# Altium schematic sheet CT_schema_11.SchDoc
size 742 x 377 mm
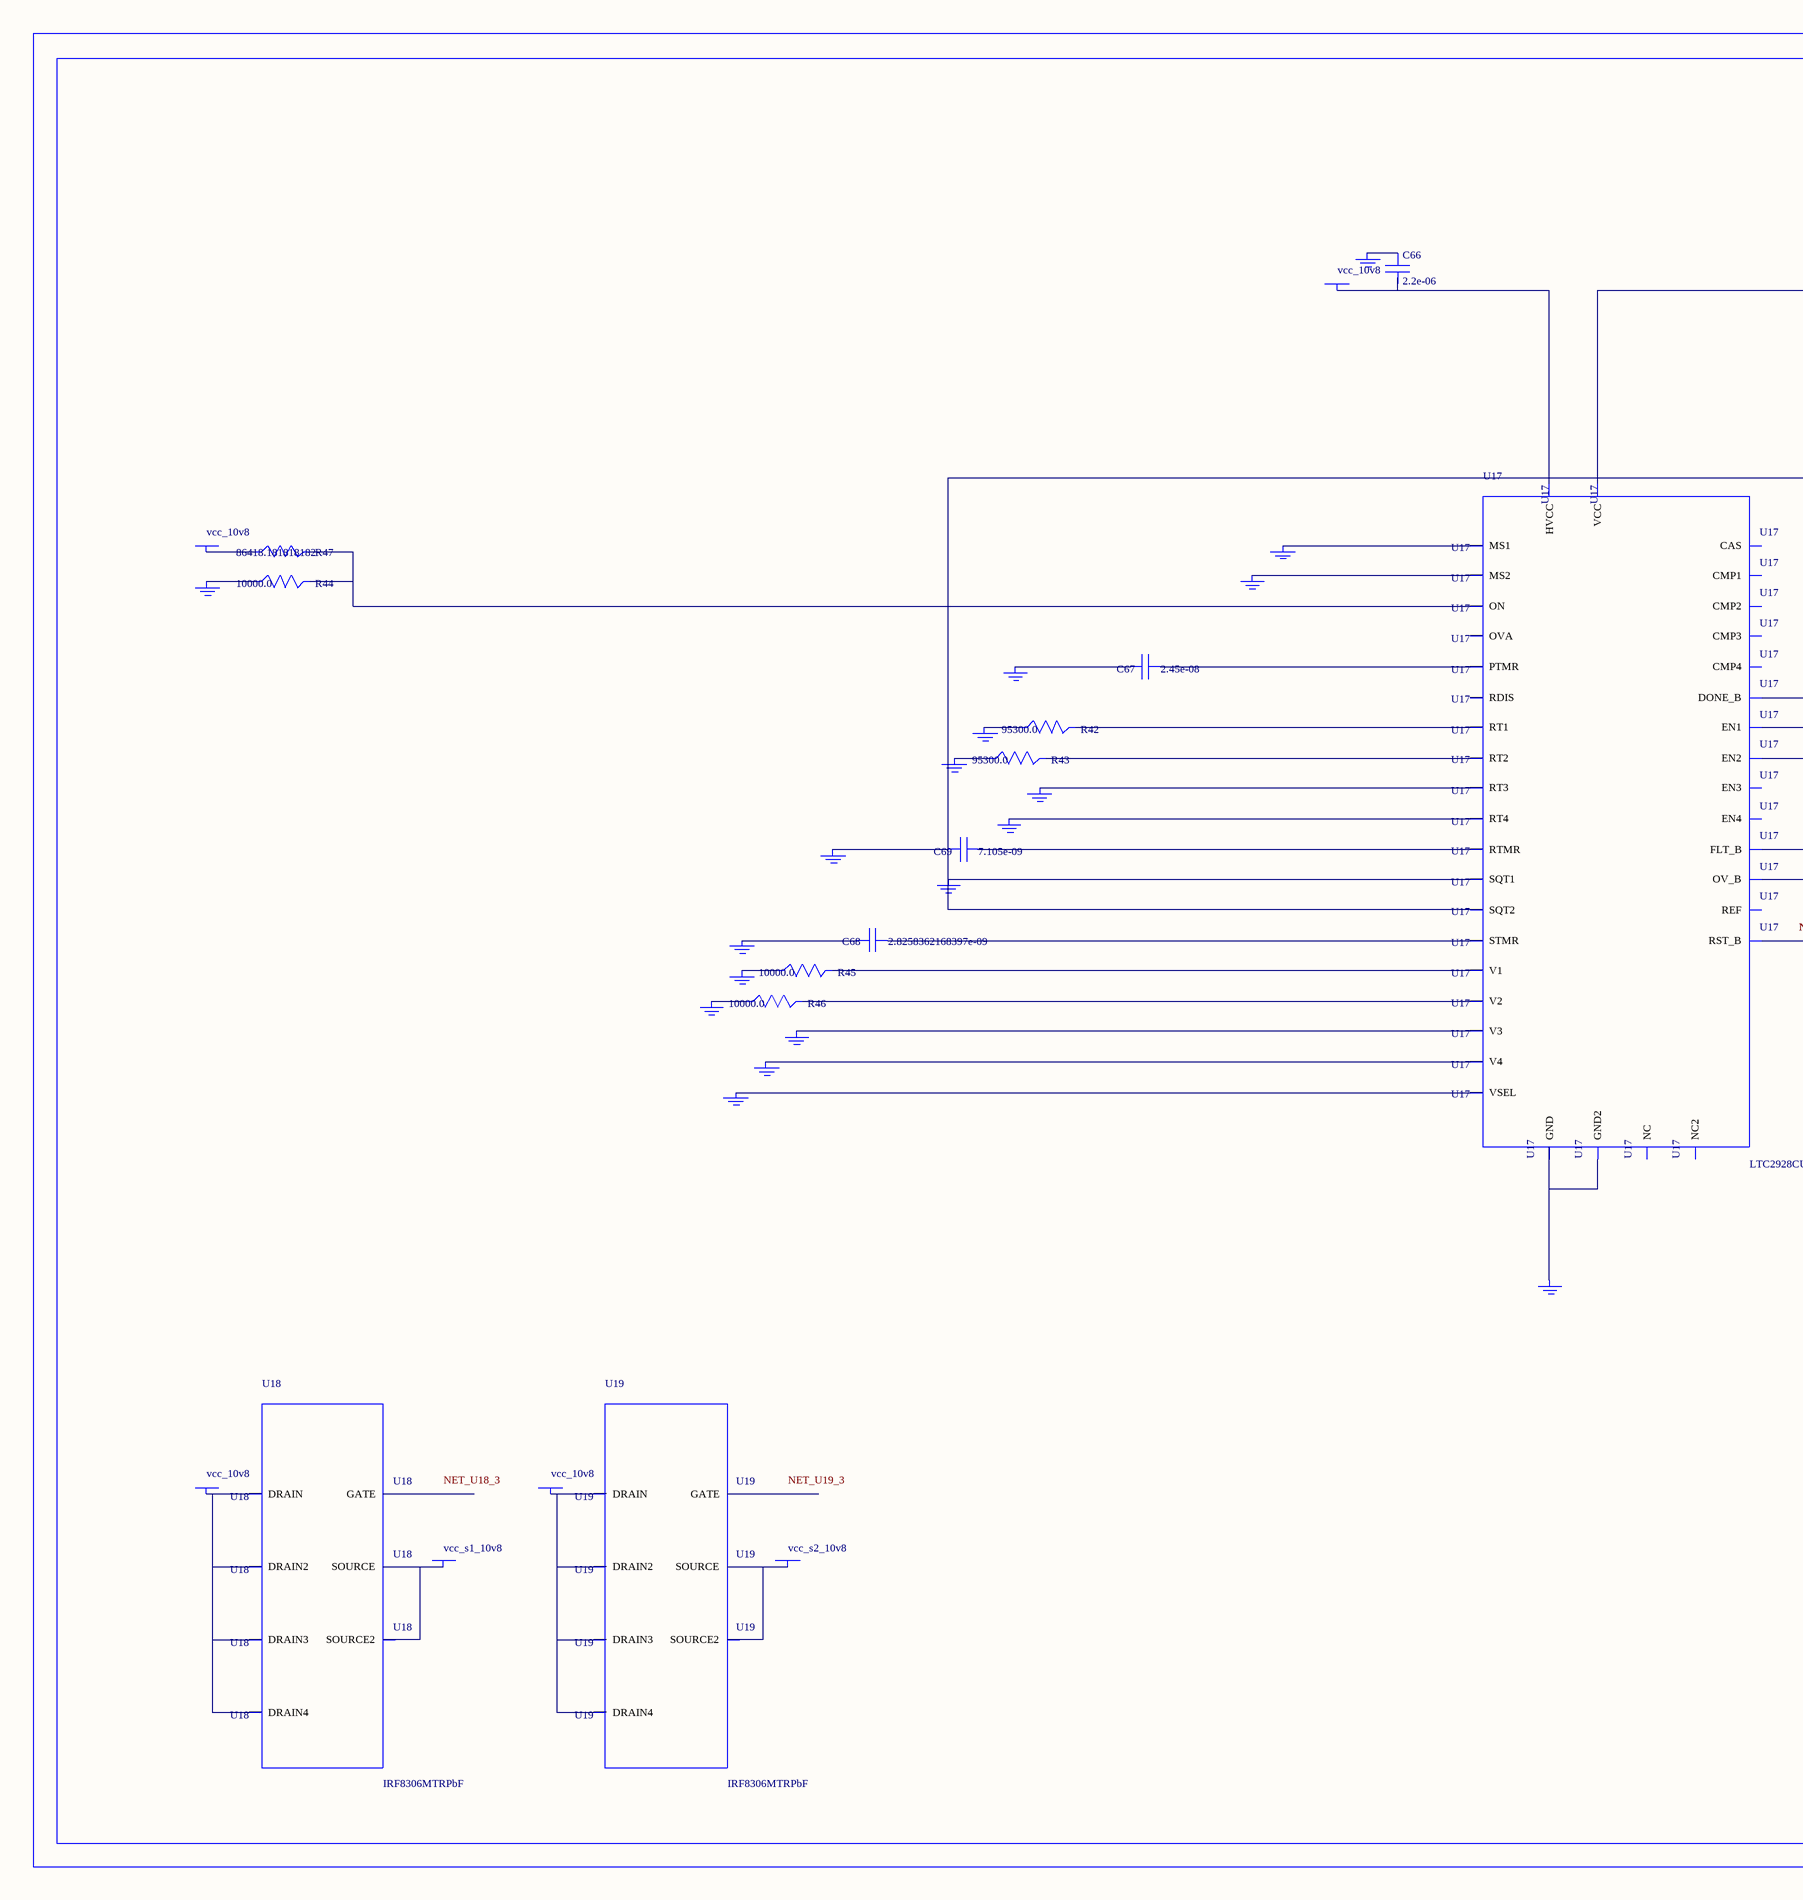
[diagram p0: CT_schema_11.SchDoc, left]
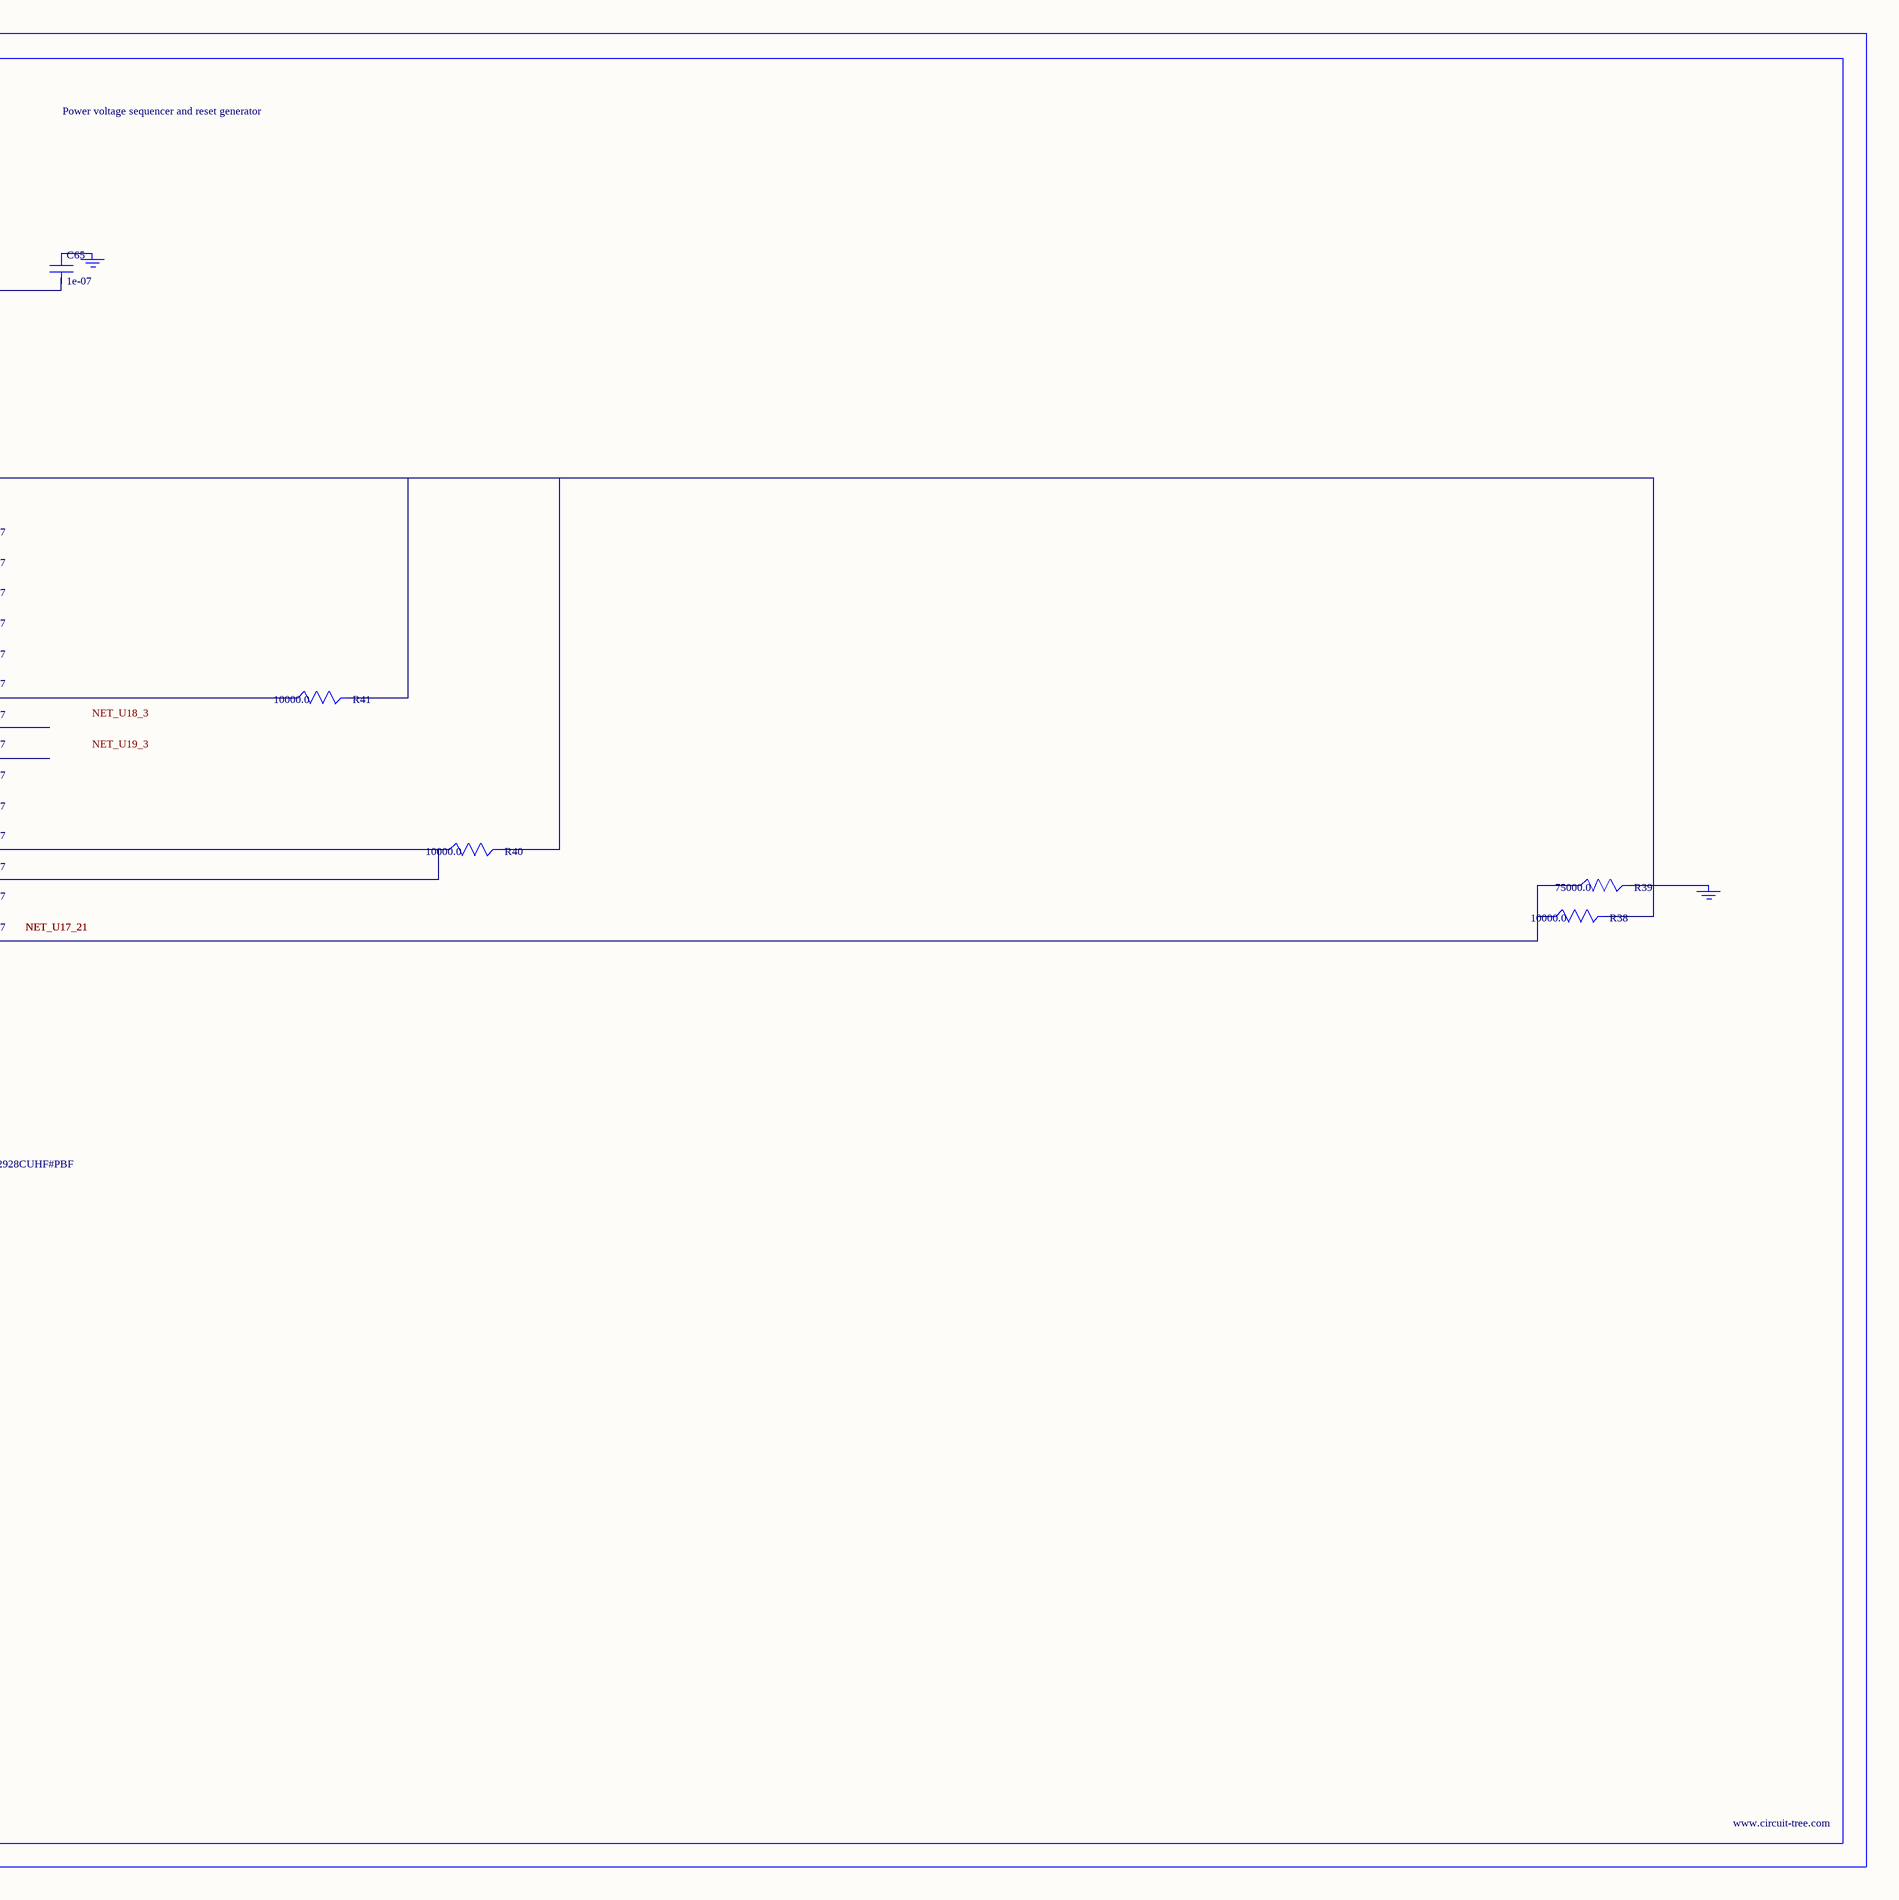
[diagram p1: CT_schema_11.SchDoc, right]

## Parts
BORDER10  (no value)
C65  1e-07  [C0402]
C66  2.2e-06  [C0603]
C67  2.45e-08  [R0603]
C68  2.8258362168397e-09  [R0603]
C69  7.105e-09  [R0603]
GND_INSTANCE_10_0  (no value)
GND_INSTANCE_10_1  (no value)
GND_INSTANCE_10_2  (no value)
GND_INSTANCE_10_3  (no value)
GND_INSTANCE_10_4  (no value)
GND_INSTANCE_10_5  (no value)
GND_INSTANCE_10_6  (no value)
GND_INSTANCE_10_7  (no value)
GND_INSTANCE_10_8  (no value)
GND_INSTANCE_10_9  (no value)
GND_INSTANCE_10_10  (no value)
GND_INSTANCE_10_11  (no value)
GND_INSTANCE_10_12  (no value)
GND_INSTANCE_10_13  (no value)
GND_INSTANCE_10_14  (no value)
GND_INSTANCE_10_15  (no value)
GND_INSTANCE_10_16  (no value)
GND_INSTANCE_10_17  (no value)
GND_INSTANCE_10_18  (no value)
GND_INSTANCE_10_19  (no value)
POWER_INSTANCE_10_0  vcc_10v8
POWER_INSTANCE_10_1  vcc_10v8
POWER_INSTANCE_10_2  vcc_10v8
POWER_INSTANCE_10_3  vcc_s1_10v8
POWER_INSTANCE_10_4  vcc_10v8
POWER_INSTANCE_10_5  vcc_s2_10v8
R38  10000.0  [R0603]
R39  75000.0  [R0603]
R40  10000.0  [R0603]
R41  10000.0  [R0603]
R42  95300.0  [R0603]
R43  95300.0  [R0603]
R44  10000.0  [R0603]
R45  10000.0  [R0603]
R46  10000.0  [R0603]
R47  86418.181818182  [R0603]
U17  LTC2928CUHF#PBF  [QFN-38_UHF]
U18  IRF8306MTRPbF  [IRF8306MTRPBF]
U19  IRF8306MTRPbF  [IRF8306MTRPBF]

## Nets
NetC65_1: C65.1 GND_INSTANCE_10_10.0(GND)
NetC65_2: C65.2 C69.2 GND_INSTANCE_10_5.0(GND) GND_INSTANCE_10_15.0(GND) R38.2 R40.2 R41.2 U17.10(SQT1) U17.11(SQT2) U17.22(VCC)
NetC66_1: C66.1 GND_INSTANCE_10_11.0(GND)
NetC66_2: C66.2 POWER_INSTANCE_10_1.0(PWR) U17.23(HVCC)
NetC67_1: C67.1 U17.27(PTMR)
NetC67_2: C67.2 GND_INSTANCE_10_14.0(GND)
NetC68_1: C68.1 U17.26(STMR)
NetC68_2: C68.2 GND_INSTANCE_10_13.0(GND)
NetC69_1: C69.1 U17.28(RTMR)
NetGND_INSTANCE_10_0_0: GND_INSTANCE_10_0.0(GND) R45.1
NetGND_INSTANCE_10_1_0: GND_INSTANCE_10_1.0(GND) R42.1
NetGND_INSTANCE_10_2_0: GND_INSTANCE_10_2.0(GND) R43.1
NetGND_INSTANCE_10_3_0: GND_INSTANCE_10_3.0(GND) U17.8(RT3)
NetGND_INSTANCE_10_4_0: GND_INSTANCE_10_4.0(GND) U17.9(RT4)
NetGND_INSTANCE_10_6_0: GND_INSTANCE_10_6.0(GND) U17.12(MS1)
NetGND_INSTANCE_10_7_0: GND_INSTANCE_10_7.0(GND) U17.13(MS2)
NetGND_INSTANCE_10_8_0: GND_INSTANCE_10_8.0(GND) R44.1
NetGND_INSTANCE_10_9_0: GND_INSTANCE_10_9.0(GND) R39.2
NetGND_INSTANCE_10_12_0: GND_INSTANCE_10_12.0(GND) U17.25(VSEL)
NetGND_INSTANCE_10_16_0: GND_INSTANCE_10_16.0(GND) U17.30(V4)
NetGND_INSTANCE_10_17_0: GND_INSTANCE_10_17.0(GND) U17.32(V3)
NetGND_INSTANCE_10_18_0: GND_INSTANCE_10_18.0(GND) R46.1
NetGND_INSTANCE_10_19_0: GND_INSTANCE_10_19.0(GND) U17.24(GND) U17.39(GND2)
NetPOWER_INSTANCE_10_0_0: POWER_INSTANCE_10_0.0(PWR) R47.1
NetPOWER_INSTANCE_10_2_0: POWER_INSTANCE_10_2.0(PWR) U18.1(DRAIN) U18.2(DRAIN2) U18.6(DRAIN3) U18.7(DRAIN4)
NetPOWER_INSTANCE_10_3_0: POWER_INSTANCE_10_3.0(PWR) U18.4(SOURCE) U18.5(SOURCE2)
NetPOWER_INSTANCE_10_4_0: POWER_INSTANCE_10_4.0(PWR) U19.1(DRAIN) U19.2(DRAIN2) U19.6(DRAIN3) U19.7(DRAIN4)
NetPOWER_INSTANCE_10_5_0: POWER_INSTANCE_10_5.0(PWR) U19.4(SOURCE) U19.5(SOURCE2)
NetR38_1: R38.1 R39.1 U17.21(RST_B)
NetR40_1: R40.1 U17.19(FLT_B) U17.20(OV_B)
NetR41_1: R41.1 U17.18(DONE_B)
NetR42_2: R42.2 U17.6(RT1)
NetR43_2: R43.2 U17.7(RT2)
NetR44_2: R44.2 R47.2 U17.16(ON)
NetR45_2: R45.2 U17.3(V1)
NetR46_2: R46.2 U17.38(V2)

Not connected (* = marked no-connect by the designer): U17 1(OVA) 2(EN1) 4(NC) 5(REF) 14(RDIS) 15(CAS) 17(NC2) 29(EN4) 31(EN3) 33(CMP3) 34(CMP4) 35(CMP1) 36(CMP2) 37(EN2); U18 3(GATE); U19 3(GATE)

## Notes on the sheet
- Labels drawn without touching a wire or pin: NET_U18_3, NET_U19_3

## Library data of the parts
BORDER10 = BORDER_PAGE10
C65 = C0402C104K3RACTU
C66 = GRM188R61H225KE1115D
C67 = C67
C68 = C68
C69 = C69
GND_INSTANCE_10_0-GND_INSTANCE_10_19 = GND
POWER_INSTANCE_10_0-POWER_INSTANCE_10_5 = PWR
R38 R40 R41 R44-R46 = RC0603JR-0710KL
R39 = RC0603JR-0775KL
R42 R43 = RC0603FR-0795K3L
R47 = R47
